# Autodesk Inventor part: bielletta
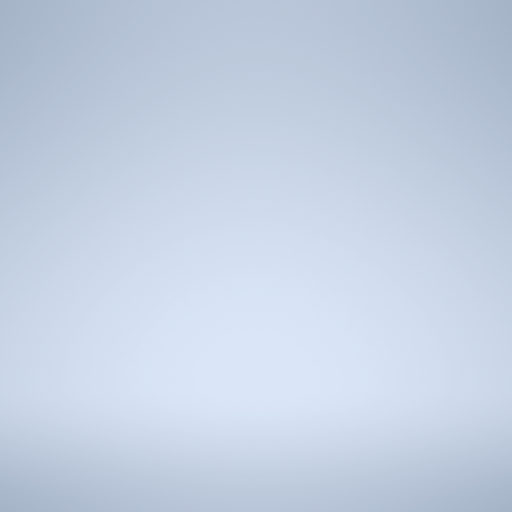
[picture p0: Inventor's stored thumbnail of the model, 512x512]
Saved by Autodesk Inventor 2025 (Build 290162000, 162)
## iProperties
Created: 2025-10
Part Number: bielletta
Material: Generico
Document SubType Name: Modeling
Designer: 18619647
Density: 1 g/cm^3
Appearance: Default
Author: 18619647
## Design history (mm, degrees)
